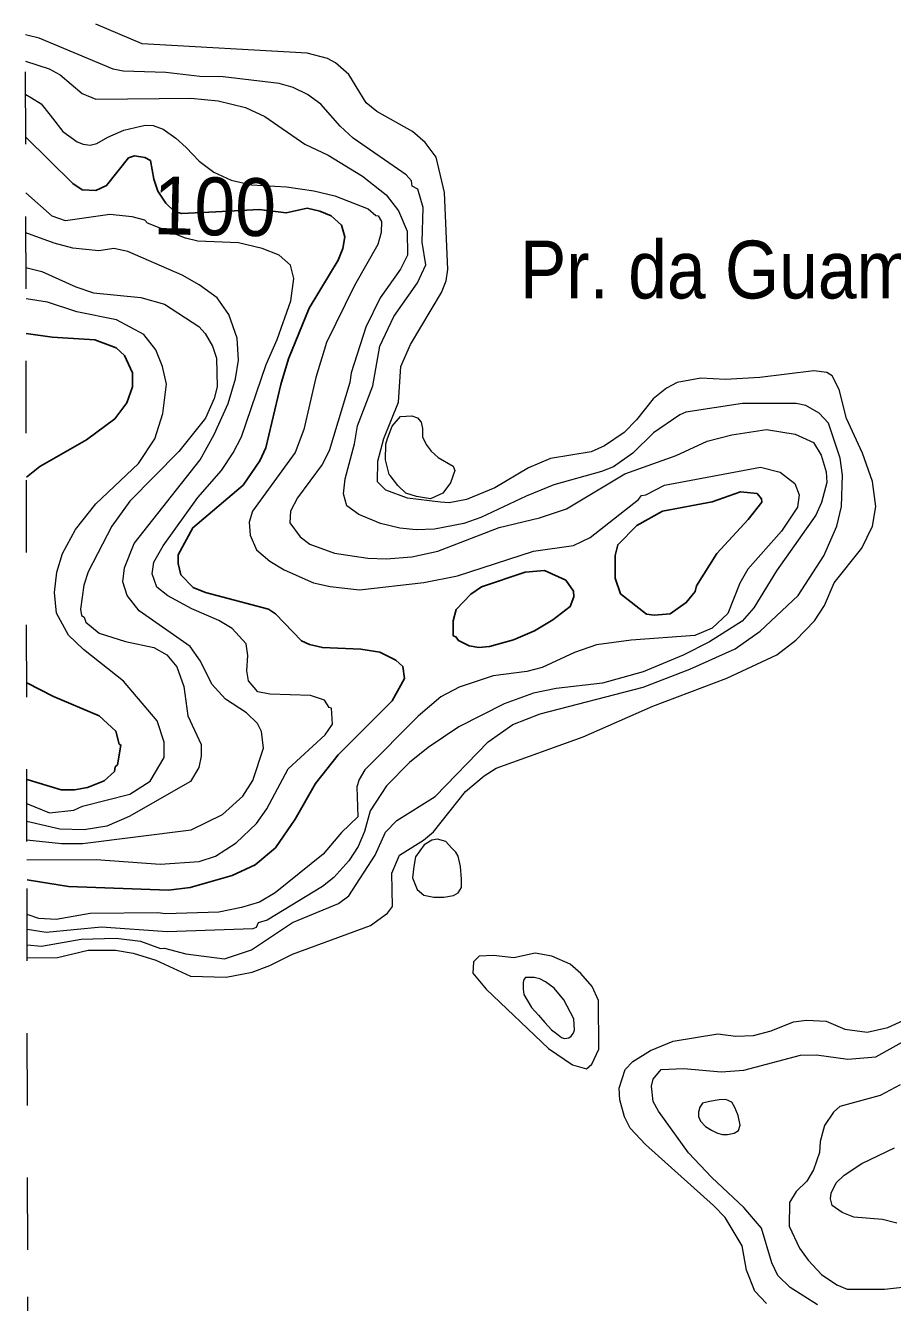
# Model space of a CAD drawing. Extents: x 474.5 to 500, y 7345.7 to 7373.4.
# Drawn here: x 474.537 to 475.736, y 7363.154 to 7364.921 of the extents above; entities that cross this region are included whole.
import ezdxf
from ezdxf.enums import TextEntityAlignment as Align

# ---------------------------------------------------------------- set-up
doc = ezdxf.new("R2010")
doc.units = 0
doc.header["$LTSCALE"] = 0.032
doc.linetypes.add('SHORT_DASHED', pattern=[2.7, 1.5, -1.2])
for name, color, linetype, lineweight in [('1', 7, 'Continuous', 25), ('15', 7, 'SHORT_DASHED', 13), ('2', 7, 'Continuous', 13), ('22', 7, 'SHORT_DASHED', 13)]:
    doc.layers.add(name, color=color, linetype=linetype, lineweight=lineweight)
doc.layers.add('61', color=7, linetype='Continuous')

msp = doc.modelspace()

# ---------------------------------------------------------------- linework, layer by layer
at = {"layer": '1'}
for points in [[(474.5392, 7363.7386), (474.5419, 7363.7382), (474.5967, 7363.7297), (474.7349, 7363.7242), (474.7648, 7363.7279), (474.8229, 7363.7449), (474.8545, 7363.7595), (474.8826, 7363.783), (474.9098, 7363.8226), (474.938, 7363.8721), (474.9694, 7363.9117), (475.044, 7363.9863), (475.0614, 7364.0171), (475.059, 7364.0337), (475.0492, 7364.0427), (475.0273, 7364.0536), (475.0007, 7364.0576), (474.9477, 7364.06), (474.9298, 7364.0641), (474.9189, 7364.0694), (474.8826, 7364.1065), (474.873, 7364.1132), (474.786, 7364.1363), (474.7691, 7364.1433), (474.752, 7364.1606), (474.748, 7364.1762), (474.748, 7364.1885), (474.7686, 7364.2258), (474.8379, 7364.2848), (474.8612, 7364.3185), (474.8693, 7364.3364), (474.89, 7364.4241), (474.9006, 7364.4596), (474.9292, 7364.5294), (474.9696, 7364.5959), (474.9761, 7364.6121), (474.9785, 7364.6281), (474.9741, 7364.6445), (474.9597, 7364.6573), (474.9439, 7364.664), (474.9268, 7364.6679), (474.8974, 7364.6616), (474.8602, 7364.6662), (474.8001, 7364.6627), (474.7529, 7364.6606), (474.7431, 7364.6635), (474.7311, 7364.6748), (474.7202, 7364.6916), (474.7144, 7364.7081), (474.7097, 7364.7338), (474.7022, 7364.7382), (474.688, 7364.7404), (474.6797, 7364.7377), (474.6492, 7364.6995), (474.6341, 7364.6922), (474.6156, 7364.6935), (474.6023, 7364.7019), (474.5374, 7364.7663)], [(474.5382, 7364.296), (474.5567, 7364.3105), (474.6214, 7364.3476), (474.6608, 7364.3765), (474.6773, 7364.3985), (474.6849, 7364.4207), (474.685, 7364.4403), (474.6741, 7364.4642), (474.6626, 7364.4749), (474.6331, 7364.486), (474.5737, 7364.4894), (474.5379, 7364.4946)], [(474.5389, 7363.8777), (474.5407, 7363.8772), (474.5865, 7363.8631), (474.6047, 7363.8631), (474.6226, 7363.8665), (474.6457, 7363.8758), (474.66, 7363.8884), (474.6611, 7363.8948), (474.6644, 7363.898), (474.6689, 7363.9251), (474.6666, 7363.9266), (474.6619, 7363.9442), (474.6389, 7363.9655), (474.5758, 7363.9923), (474.5387, 7364.0112)]]:
    msp.add_lwpolyline(points, dxfattribs=at)
for points in [[(475.4181, 7364.2489), (475.3827, 7364.2289), (475.3561, 7364.2023), (475.3526, 7364.1874), (475.3526, 7364.1561), (475.3599, 7364.1343), (475.396, 7364.1063), (475.4063, 7364.1048), (475.4287, 7364.1065), (475.4508, 7364.1223), (475.4634, 7364.1376), (475.4652, 7364.1453), (475.493, 7364.1904), (475.5367, 7364.2372), (475.5553, 7364.2613), (475.5549, 7364.2658), (475.5489, 7364.273), (475.5259, 7364.2754), (475.4867, 7364.2618)], [(475.1679, 7364.1439), (475.1529, 7364.1337), (475.1326, 7364.1129), (475.1286, 7364.097), (475.1286, 7364.0764), (475.1324, 7364.0751), (475.1357, 7364.0696), (475.1507, 7364.0623), (475.1641, 7364.0601), (475.179, 7364.0617), (475.2119, 7364.0709), (475.2408, 7364.083), (475.2665, 7364.0983), (475.2903, 7364.1168), (475.2952, 7364.1302), (475.2949, 7364.1379), (475.2842, 7364.1532), (475.2547, 7364.1668), (475.2282, 7364.1645)]]:
    msp.add_lwpolyline(points, close=True, dxfattribs=at)
at = {"layer": '15'}
for points in [[(475.0349, 7364.3198), (475.0353, 7364.3416), (475.0376, 7364.3495), (475.044, 7364.3663), (475.0555, 7364.3796), (475.0713, 7364.3808)], [(475.0713, 7364.3808), (475.0794, 7364.3779), (475.0841, 7364.3721), (475.086, 7364.3629)], [(475.086, 7364.3629), (475.086, 7364.3516), (475.0914, 7364.3408), (475.0981, 7364.3316), (475.1077, 7364.3232), (475.1286, 7364.3111), (475.1309, 7364.3051)], [(475.1309, 7364.3051), (475.1248, 7364.2879), (475.1143, 7364.2736), (475.0972, 7364.2658), (475.0779, 7364.269), (475.0631, 7364.2736), (475.052, 7364.2844), (475.0415, 7364.2979), (475.04, 7364.2995), (475.0402, 7364.2993), (475.0349, 7364.3198)]]:
    msp.add_lwpolyline(points, dxfattribs=at)
msp.add_lwpolyline([(475.1264, 7363.7831), (475.1185, 7363.7917), (475.107, 7363.7951), (475.099, 7363.7938), (475.0884, 7363.7872), (475.0765, 7363.7706), (475.0739, 7363.7573), (475.0725, 7363.7414), (475.0785, 7363.7255), (475.0878, 7363.7176), (475.1017, 7363.7149), (475.1156, 7363.7149), (475.1288, 7363.7169), (475.1354, 7363.7209), (475.1401, 7363.7282), (475.1401, 7363.7394), (475.1386, 7363.7572), (475.1353, 7363.7714), (475.1321, 7363.7768)], close=True, dxfattribs=at)
at = {"layer": '2'}
for points in [[(474.5394, 7363.6309), (474.5814, 7363.6312), (474.6238, 7363.6413), (474.6616, 7363.6413), (474.686, 7363.6372), (474.7174, 7363.6277), (474.7653, 7363.6054), (474.8146, 7363.6041), (474.8504, 7363.611), (474.8749, 7363.6201), (474.9062, 7363.6357), (475.0141, 7363.6753), (475.0379, 7363.6928), (475.0447, 7363.7019), (475.0438, 7363.748), (475.0542, 7363.7726), (475.0876, 7363.7935), (475.1011, 7363.8053), (475.1456, 7363.861), (475.1713, 7363.8825), (475.1881, 7363.8932), (475.3083, 7363.9365), (475.4046, 7363.979), (475.5072, 7364.0176), (475.5763, 7364.0501), (475.6026, 7364.0701), (475.6281, 7364.097), (475.6419, 7364.1184), (475.6555, 7364.1496), (475.6935, 7364.1975), (475.7085, 7364.2279), (475.7132, 7364.2553), (475.7084, 7364.2898), (475.6945, 7364.3289), (475.6727, 7364.377), (475.6623, 7364.4172), (475.6525, 7364.4358), (475.6452, 7364.4405), (475.6274, 7364.4429), (475.5527, 7364.4335), (475.5052, 7364.4311), (475.471, 7364.4326), (475.4382, 7364.4266), (475.4234, 7364.4189), (475.405, 7364.4043), (475.382, 7364.3749), (475.3648, 7364.3578), (475.3376, 7364.3389), (475.3194, 7364.331), (475.263, 7364.3218), (475.2328, 7364.3088), (475.1862, 7364.2808), (475.1471, 7364.2651), (475.1232, 7364.2604), (475.1109, 7364.2612), (475.0653, 7364.2667), (475.0354, 7364.2777), (475.0239, 7364.2891), (475.0241, 7364.318), (475.0326, 7364.3494), (475.0527, 7364.3997), (475.0563, 7364.4491), (475.0693, 7364.4794), (475.1124, 7364.5512), (475.1189, 7364.5675), (475.1213, 7364.5832), (475.1166, 7364.6898), (475.105, 7364.7386), (475.0896, 7364.7587), (475.0724, 7364.7742), (475.0228, 7364.8018), (475.0084, 7364.8137), (474.9841, 7364.853), (474.9657, 7364.8689), (474.9545, 7364.8749), (474.9265, 7364.8826), (474.6983, 7364.8954), (474.6345, 7364.9225)], [(474.5394, 7363.6487), (474.559, 7363.6469), (474.6142, 7363.6565), (474.6624, 7363.658), (474.6959, 7363.6539), (474.7236, 7363.6438), (474.7294, 7363.6443), (474.759, 7363.6361), (474.8123, 7363.6293), (474.8496, 7363.6418), (474.9064, 7363.6798), (474.9699, 7363.706), (474.9843, 7363.7164), (475.0207, 7363.7726), (475.0351, 7363.8047), (475.0506, 7363.8209), (475.1036, 7363.8541), (475.1767, 7363.9296), (475.2112, 7363.9538), (475.2489, 7363.9683), (475.3912, 7364.0051), (475.4557, 7364.0301), (475.5184, 7364.0583), (475.5533, 7364.0829), (475.6057, 7364.1319), (475.641, 7364.1871), (475.6592, 7364.2282), (475.6655, 7364.2553), (475.667, 7364.2984), (475.6638, 7364.322), (475.6478, 7364.3703), (475.6348, 7364.3843), (475.6164, 7364.3951), (475.6031, 7364.3975), (475.5288, 7364.3976), (475.4503, 7364.3856), (475.4419, 7364.3822), (475.4058, 7364.3572), (475.3768, 7364.3291), (475.3504, 7364.3102), (475.3338, 7364.3034), (475.2678, 7364.2851), (475.2293, 7364.2696), (475.1669, 7364.2399), (475.1434, 7364.2319), (475.1028, 7364.2237), (475.0773, 7364.2229), (475.0546, 7364.2252), (475.0278, 7364.2317), (474.9982, 7364.244), (474.9813, 7364.2562), (474.9769, 7364.2726), (474.979, 7364.2933), (474.992, 7364.3419), (474.9962, 7364.3667), (475.0176, 7364.4223), (475.0269, 7364.4768), (475.0465, 7364.5181), (475.0791, 7364.5645), (475.0909, 7364.5895), (475.0855, 7364.6211), (475.0871, 7364.669), (475.0796, 7364.6943), (475.0718, 7364.6985), (475.0707, 7364.7059), (475.0635, 7364.714), (474.9903, 7364.7646), (474.9721, 7364.7812), (474.9454, 7364.8119), (474.927, 7364.825), (474.9073, 7364.8347), (474.8879, 7364.8403), (474.8105, 7364.8498), (474.7781, 7364.8499), (474.731, 7364.8554), (474.6719, 7364.8575), (474.6581, 7364.8604), (474.5558, 7364.9029), (474.5371, 7364.9079)], [(474.5372, 7364.8714), (474.5696, 7364.8609), (474.5852, 7364.8522), (474.6155, 7364.8264), (474.6342, 7364.8189), (474.7658, 7364.8203), (474.8033, 7364.8164), (474.8411, 7364.8073), (474.8679, 7364.7947), (474.9233, 7364.7567), (474.9557, 7364.7412), (475.003, 7364.712), (475.036, 7364.6862), (475.053, 7364.6642), (475.0647, 7364.636), (475.0654, 7364.6031), (475.0559, 7364.5835), (475.0274, 7364.5437), (475.0079, 7364.5034), (474.9874, 7364.4401), (474.9858, 7364.4267), (474.9568, 7364.3324), (474.9473, 7364.3135), (474.9133, 7364.2673), (474.9036, 7364.2486), (474.9028, 7364.2324), (474.9168, 7364.213), (474.9305, 7364.2033), (474.9643, 7364.1907), (475.0107, 7364.1838), (475.036, 7364.183), (475.0715, 7364.1857), (475.1072, 7364.1933), (475.1921, 7364.226), (475.2477, 7364.2396), (475.2851, 7364.2521), (475.3659, 7364.3004), (475.4369, 7364.3257), (475.48, 7364.3457), (475.5141, 7364.3545), (475.5617, 7364.3616), (475.6014, 7364.3553), (475.627, 7364.3439), (475.6375, 7364.3263), (475.6445, 7364.3031), (475.6455, 7364.2886), (475.6378, 7364.2605), (475.6302, 7364.2433), (475.5758, 7364.1663), (475.5444, 7364.1148), (475.5283, 7364.0965), (475.4832, 7364.0678), (475.4466, 7364.0495), (475.3912, 7364.0266), (475.3349, 7364.0106), (475.2711, 7364.0034), (475.2397, 7363.9971), (475.199, 7363.9824), (475.1362, 7363.9502), (475.0939, 7363.9216), (475.0683, 7363.901), (475.0361, 7363.8688), (475.0139, 7363.8341), (475.006, 7363.8057), (474.9971, 7363.7847), (474.9841, 7363.7652), (474.9635, 7363.7419), (474.948, 7363.7297), (474.8712, 7363.6827), (474.8589, 7363.6793), (474.856, 7363.6729), (474.8516, 7363.6708), (474.7329, 7363.6668), (474.6423, 7363.6732), (474.5654, 7363.666), (474.5393, 7363.6699)], [(474.5373, 7364.8251), (474.5452, 7364.8204), (474.5587, 7364.8121), (474.5712, 7364.7965), (474.5886, 7364.774), (474.6087, 7364.7598), (474.6166, 7364.7567), (474.6267, 7364.755), (474.6355, 7364.7574), (474.6511, 7364.766), (474.673, 7364.7757), (474.6965, 7364.7816), (474.7031, 7364.7826), (474.7135, 7364.7823), (474.7274, 7364.7774), (474.7451, 7364.7646), (474.7594, 7364.7519), (474.7774, 7364.7328), (474.7975, 7364.7179), (474.8217, 7364.7065), (474.8495, 7364.7004), (474.8982, 7364.6974), (474.9357, 7364.6919), (474.9647, 7364.6848), (475.011, 7364.6671), (475.0216, 7364.6578), (475.0248, 7364.6574), (475.0296, 7364.6494), (475.0288, 7364.6344), (475.0242, 7364.6175), (474.992, 7364.5608), (474.9534, 7364.4821), (474.9387, 7364.4337), (474.922, 7364.3619), (474.91, 7364.33), (474.8511, 7364.2486), (474.8465, 7364.2337), (474.8479, 7364.2154), (474.8563, 7364.1951), (474.8748, 7364.1795), (474.895, 7364.1676), (474.9352, 7364.1496), (474.9586, 7364.1443), (474.9991, 7364.1399), (475.0878, 7364.1502), (475.1344, 7364.1594), (475.2397, 7364.1933), (475.295, 7364.2012), (475.3181, 7364.2123), (475.3849, 7364.2648), (475.3888, 7364.2705), (475.3949, 7364.2715), (475.4207, 7364.2846), (475.5535, 7364.3097), (475.5807, 7364.3029), (475.6012, 7364.287), (475.607, 7364.2712), (475.6048, 7364.2545), (475.5828, 7364.2211), (475.536, 7364.1683), (475.5248, 7364.1489), (475.5083, 7364.1073), (475.4865, 7364.087), (475.4627, 7364.0769), (475.3748, 7364.0704), (475.3269, 7364.064), (475.2961, 7364.0532), (475.2515, 7364.0325), (475.2305, 7364.0271), (475.1838, 7364.021), (475.1367, 7364.0054), (475.1114, 7363.9917), (475.08, 7363.9653), (475.0063, 7363.8907), (474.9983, 7363.8777), (474.9954, 7363.8673), (474.9965, 7363.8259), (474.9739, 7363.8041), (474.9486, 7363.774), (474.8824, 7363.7207), (474.8605, 7363.7079), (474.8357, 7363.7002), (474.8044, 7363.694), (474.7307, 7363.6916), (474.7202, 7363.6932), (474.6267, 7363.6923), (474.5794, 7363.6836), (474.5556, 7363.6854), (474.5393, 7363.6907)], [(474.5391, 7363.7662), (474.6347, 7363.7668), (474.7234, 7363.7602), (474.777, 7363.7642), (474.7996, 7363.7715), (474.8285, 7363.7898), (474.8563, 7363.8165), (474.871, 7363.837), (474.9002, 7363.8923), (474.9515, 7363.9393), (474.9615, 7363.9539), (474.9601, 7363.976), (474.957, 7363.9773), (474.9505, 7363.9874), (474.9314, 7363.9938), (474.875, 7363.9955), (474.8583, 7363.9986), (474.8456, 7364.014), (474.843, 7364.0278), (474.8445, 7364.0492), (474.8421, 7364.0653), (474.8227, 7364.0866), (474.8045, 7364.0975), (474.7669, 7364.1136), (474.7339, 7364.1314), (474.7188, 7364.1435), (474.7122, 7364.1621), (474.7146, 7364.1781), (474.7274, 7364.2007), (474.7753, 7364.2676), (474.808, 7364.3052), (474.8244, 7364.3295), (474.8356, 7364.3518), (474.8697, 7364.4515), (474.8853, 7364.4863), (474.9042, 7364.5397), (474.9083, 7364.5706), (474.9035, 7364.5889), (474.888, 7364.603), (474.8642, 7364.6122), (474.8315, 7364.62), (474.7752, 7364.6225), (474.7585, 7364.6264), (474.7058, 7364.6474), (474.702, 7364.6513), (474.6847, 7364.6558), (474.6536, 7364.6591), (474.5922, 7364.6506), (474.5741, 7364.6568), (474.5375, 7364.689)], [(474.5391, 7363.7942), (474.5869, 7363.7889), (474.616, 7363.789), (474.7663, 7363.808), (474.8093, 7363.8289), (474.8375, 7363.8545), (474.8516, 7363.8763), (474.866, 7363.921), (474.8636, 7363.9437), (474.858, 7363.9548), (474.8428, 7363.9699), (474.8135, 7363.9887), (474.7947, 7364.0096), (474.779, 7364.0412), (474.7648, 7364.0616), (474.6941, 7364.1108), (474.6776, 7364.1321), (474.6715, 7364.1508), (474.6739, 7364.1704), (474.6872, 7364.2042), (474.7788, 7364.3196), (474.7979, 7364.3546), (474.8172, 7364.3977), (474.8277, 7364.4316), (474.8318, 7364.4578), (474.83, 7364.4882), (474.8183, 7364.5209), (474.8021, 7364.5437), (474.7773, 7364.562), (474.7538, 7364.5753), (474.6784, 7364.6079), (474.6592, 7364.612), (474.6386, 7364.609), (474.6027, 7364.6126), (474.5767, 7364.6194), (474.5376, 7364.634)], [(474.5377, 7364.5859), (474.5598, 7364.5802), (474.6068, 7364.559), (474.6313, 7364.5507), (474.6964, 7364.5444), (474.7295, 7364.5351), (474.7767, 7364.5043), (474.7857, 7364.4944), (474.7957, 7364.4768), (474.8014, 7364.4605), (474.8022, 7364.4206), (474.7982, 7364.4045), (474.7862, 7364.3776), (474.7493, 7364.3311), (474.6813, 7364.2624), (474.6564, 7364.2278), (474.6239, 7364.1646), (474.6176, 7364.1465), (474.6132, 7364.1131), (474.6147, 7364.1042), (474.618, 7364.1021), (474.6204, 7364.0952), (474.639, 7364.0799), (474.6755, 7364.0686), (474.7143, 7364.0601), (474.7324, 7364.0502), (474.7463, 7364.0332), (474.7559, 7364.0061), (474.7617, 7363.9654), (474.7799, 7363.926), (474.7799, 7363.9098), (474.7766, 7363.8939), (474.7651, 7363.8747), (474.6806, 7363.8262), (474.6493, 7363.8128), (474.618, 7363.808), (474.5847, 7363.8088), (474.5391, 7363.8195)], [(474.539, 7363.8443), (474.5399, 7363.8439), (474.5704, 7363.8313), (474.6041, 7363.835), (474.6158, 7363.8407), (474.6815, 7363.8571), (474.7093, 7363.8753), (474.7288, 7363.908), (474.7288, 7363.9292), (474.7191, 7363.9587), (474.6727, 7364.0134), (474.6174, 7364.0572), (474.5966, 7364.0774), (474.58, 7364.1078), (474.5773, 7364.136), (474.5806, 7364.1643), (474.5884, 7364.1903), (474.6061, 7364.2235), (474.6341, 7364.2589), (474.6933, 7364.3149), (474.7159, 7364.3486), (474.7268, 7364.3839), (474.7321, 7364.4245), (474.7265, 7364.4491), (474.7175, 7364.472), (474.7009, 7364.4932), (474.6629, 7364.5133), (474.6082, 7364.5245), (474.5675, 7364.538), (474.5378, 7364.5427)], [(475.5617, 7363.1524), (475.5456, 7363.1694), (475.5341, 7363.1987), (475.5281, 7363.2323), (475.5046, 7363.2714), (475.4888, 7363.2882), (475.3947, 7363.3726), (475.3731, 7363.3952), (475.3654, 7363.4107), (475.3591, 7363.4341), (475.3583, 7363.4505), (475.3664, 7363.4763), (475.3772, 7363.4873), (475.4014, 7363.5024), (475.4327, 7363.5153), (475.4944, 7363.5256), (475.5193, 7363.5224), (475.5439, 7363.5231), (475.5683, 7363.5296), (475.5991, 7363.5421), (475.617, 7363.5447), (475.6446, 7363.5431), (475.67, 7363.5323), (475.7011, 7363.528), (475.7295, 7363.5345), (475.7628, 7363.5495)], [(475.6325, 7363.1508), (475.5948, 7363.1749), (475.5777, 7363.1913), (475.5693, 7363.209), (475.5551, 7363.2569), (475.5307, 7363.2852), (475.4861, 7363.3267), (475.454, 7363.3611), (475.4127, 7363.4186), (475.4053, 7363.4321), (475.403, 7363.4531), (475.4053, 7363.4631), (475.4163, 7363.4762), (475.4474, 7363.4777), (475.4993, 7363.473), (475.5305, 7363.4752), (475.609, 7363.4961), (475.6309, 7363.4968), (475.6743, 7363.4905), (475.7131, 7363.4938), (475.7769, 7363.5294)], [(475.7468, 7363.455), (475.7193, 7363.4401), (475.6631, 7363.4249), (475.6546, 7363.4173), (475.6423, 7363.3987), (475.6359, 7363.3769), (475.6351, 7363.3613), (475.6271, 7363.3373), (475.6178, 7363.3218), (475.6028, 7363.3073), (475.5936, 7363.2924), (475.5931, 7363.2594), (475.6077, 7363.2293), (475.6195, 7363.2124), (475.6378, 7363.1928), (475.6591, 7363.1783), (475.6734, 7363.1722), (475.725, 7363.1722), (475.7745, 7363.1778)], [(475.742, 7363.2639), (475.7223, 7363.2688), (475.6827, 7363.2719), (475.6665, 7363.2785), (475.6526, 7363.2883), (475.6503, 7363.2972), (475.6511, 7363.3054), (475.6581, 7363.3195), (475.6692, 7363.33), (475.6935, 7363.3461), (475.7391, 7363.3681)]]:
    msp.add_lwpolyline(points, dxfattribs=at)
for points in [[(475.2649, 7363.633), (475.2421, 7363.6371), (475.2125, 7363.6309), (475.1841, 7363.634), (475.1645, 7363.6332), (475.1565, 7363.6251), (475.1557, 7363.6094), (475.1743, 7363.5874), (475.2606, 7363.5052), (475.2934, 7363.4826), (475.3127, 7363.4771), (475.3201, 7363.4835), (475.3302, 7363.5043), (475.3295, 7363.5718), (475.3206, 7363.5911), (475.3053, 7363.6089), (475.2902, 7363.6219)], [(475.2261, 7363.5799), (475.237, 7363.5622), (475.2465, 7363.5513), (475.2555, 7363.5411), (475.2646, 7363.5313), (475.2713, 7363.526), (475.2785, 7363.5207), (475.2827, 7363.5192), (475.2857, 7363.5196), (475.2887, 7363.5203), (475.2917, 7363.5222), (475.2947, 7363.526), (475.2962, 7363.5309), (475.2955, 7363.5464), (475.2815, 7363.5727), (475.268, 7363.5889), (475.2563, 7363.5976), (475.2484, 7363.6018), (475.2404, 7363.6036), (475.2344, 7363.6036), (475.2287, 7363.6036), (475.2261, 7363.6006), (475.2254, 7363.5965), (475.2254, 7363.5874)], [(475.4677, 7363.4174), (475.468, 7363.4114), (475.4707, 7363.4046), (475.4775, 7363.3975), (475.4858, 7363.3922), (475.4941, 7363.388), (475.5009, 7363.3865), (475.5081, 7363.3865), (475.5171, 7363.3884), (475.5231, 7363.3918), (475.5254, 7363.3993), (475.5228, 7363.4125), (475.5182, 7363.4235), (475.5141, 7363.431), (475.5054, 7363.4348), (475.4964, 7363.4344), (475.4832, 7363.4321), (475.4734, 7363.4295), (475.4696, 7363.4242)]]:
    msp.add_lwpolyline(points, close=True, dxfattribs=at)
at = {"layer": '22'}
msp.add_lwpolyline([(474.5471, 7359.2727), (474.5461, 7359.8375), (474.5451, 7360.4024), (474.5441, 7360.9673), (474.5431, 7361.5321), (474.5421, 7362.097), (474.5411, 7362.6619), (474.5401, 7363.2267), (474.5391, 7363.7916), (474.5381, 7364.3565), (474.5371, 7364.9213)], dxfattribs=at)

# ---------------------------------------------------------------- texts
at = {"layer": '61', "width": 0.95}
msp.add_text('100', height=0.08, rotation=358.977, dxfattribs=at).set_placement((474.7981, 7364.6304), align=Align.CENTER)
at = {"layer": '61', "width": 0.9}
msp.add_text('Pr. da Guamixama', height=0.08, dxfattribs=at).set_placement((475.6221, 7364.543), align=Align.CENTER)

doc.saveas('drawing.dxf')
